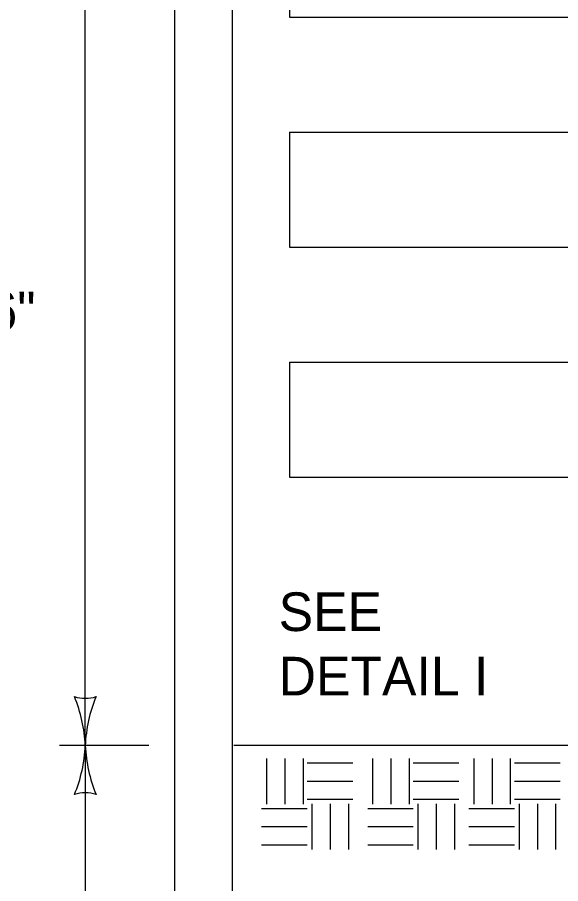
# Model space of a CAD drawing. Extents: x 49991.4 to 50021, y 49987.6 to 50011.4.
# Drawn here: x 50008.713 to 50009.557, y 49995.941 to 49997.286 of the extents above; entities that cross this region are included whole.
import ezdxf

# ---------------------------------------------------------------- set-up
doc = ezdxf.new("R2010")
doc.units = 0
for name, color, linetype in [('Level 1', 7, 'Continuous'), ('Level 2', 7, 'Continuous'), ('Level 3', 7, 'Continuous')]:
    doc.layers.add(name, color=color, linetype=linetype)

msp = doc.modelspace()

# ---------------------------------------------------------------- linework, layer by layer
at = {"layer": 'Level 1'}
for p, q in [((50009.1361, 49997.464), (50009.1361, 49997.2855)), ((50008.9574, 49997.4044), (50008.9574, 49995.084)), ((50009.0467, 49997.4044), (50009.0467, 49995.084)), ((50009.1361, 49997.2855), (50013.48, 49997.2855)), ((50009.1361, 49997.107), (50009.1361, 49996.9285)), ((50009.1361, 49997.107), (50013.735, 49997.107)), ((50009.1361, 49996.9285), (50013.9899, 49996.9285)), ((50009.1361, 49996.75), (50009.1361, 49996.5715)), ((50009.1361, 49996.75), (50014.2449, 49996.75)), ((50009.1361, 49996.5715), (50014.8571, 49996.5715)), ((50009.8066, 49996.155), (50009.0495, 49996.155)), ((50009.1002, 49996.135), (50009.1002, 49996.0641)), ((50009.1285, 49996.135), (50009.1285, 49996.0641)), ((50009.1569, 49996.135), (50009.1569, 49996.0641)), ((50009.2649, 49996.135), (50009.2649, 49996.0641)), ((50009.2932, 49996.135), (50009.2932, 49996.0641)), ((50009.3216, 49996.135), (50009.3216, 49996.0641)), ((50009.4221, 49996.135), (50009.4221, 49996.0641)), ((50009.4504, 49996.135), (50009.4504, 49996.0641)), ((50009.4788, 49996.135), (50009.4788, 49996.0641)), ((50009.1634, 49996.1283), (50009.2343, 49996.1283)), ((50009.3282, 49996.1283), (50009.3991, 49996.1283)), ((50009.4853, 49996.1283), (50009.5562, 49996.1283)), ((50009.1634, 49996.1), (50009.2343, 49996.1)), ((50009.3282, 49996.1), (50009.3991, 49996.1)), ((50009.4853, 49996.1), (50009.5562, 49996.1)), ((50009.1634, 49996.0717), (50009.2343, 49996.0717)), ((50009.1705, 49996.0646), (50009.1705, 49995.9937)), ((50009.1989, 49996.0646), (50009.1989, 49995.9937)), ((50009.2273, 49996.0646), (50009.2273, 49995.9937)), ((50009.3282, 49996.0717), (50009.3991, 49996.0717)), ((50009.3352, 49996.0646), (50009.3352, 49995.9937)), ((50009.3636, 49996.0646), (50009.3636, 49995.9937)), ((50009.392, 49996.0646), (50009.392, 49995.9937)), ((50009.4853, 49996.0717), (50009.5562, 49996.0717)), ((50009.4924, 49996.0646), (50009.4924, 49995.9937)), ((50009.5208, 49996.0646), (50009.5208, 49995.9937)), ((50009.5492, 49996.0646), (50009.5492, 49995.9937)), ((50009.0926, 49996.0575), (50009.1634, 49996.0575)), ((50009.2573, 49996.0575), (50009.3282, 49996.0575)), ((50009.4145, 49996.0575), (50009.4853, 49996.0575)), ((50009.0926, 49996.0292), (50009.1634, 49996.0292)), ((50009.2573, 49996.0292), (50009.3282, 49996.0292)), ((50009.4145, 49996.0292), (50009.4853, 49996.0292)), ((50009.0926, 49996.0008), (50009.1634, 49996.0008)), ((50009.2573, 49996.0008), (50009.3282, 49996.0008)), ((50009.4145, 49996.0008), (50009.4853, 49996.0008))]:
    msp.add_line(p, q, dxfattribs=at)
at = {"layer": 'Level 3'}
for p, q in [((50008.8188, 49996.155), (50008.8188, 49997.405)), ((50008.9174, 49996.155), (50008.7788, 49996.155)), ((50008.8188, 49996.155), (50008.8188, 49995.084))]:
    msp.add_line(p, q, dxfattribs=at)
for centre, radius, start, end in [((50008.8188, 49996.2832), 0.0548, 252.1388, 287.8612), ((50008.5861, 49996.1435), 0.233, 2.8273, 22.0772), ((50009.0409, 49996.1458), 0.2223, 157.456, 177.6395), ((50008.5967, 49996.1642), 0.2223, 337.456, 357.6395), ((50009.0515, 49996.1665), 0.233, 182.8273, 202.0772), ((50008.8188, 49996.0268), 0.0548, 72.1388, 107.8612)]:
    msp.add_arc(centre, radius, start, end, dxfattribs=at)

# ---------------------------------------------------------------- texts
at = {"layer": 'Level 2'}
for s, p in [('3\'-6"', (50008.5819, 49996.7997)), ('SEE', (50009.1191, 49996.3328)), ('DETAIL I', (50009.1191, 49996.2328))]:
    msp.add_text(s, height=0.06, dxfattribs=at).set_placement(p)

doc.saveas('drawing.dxf')
